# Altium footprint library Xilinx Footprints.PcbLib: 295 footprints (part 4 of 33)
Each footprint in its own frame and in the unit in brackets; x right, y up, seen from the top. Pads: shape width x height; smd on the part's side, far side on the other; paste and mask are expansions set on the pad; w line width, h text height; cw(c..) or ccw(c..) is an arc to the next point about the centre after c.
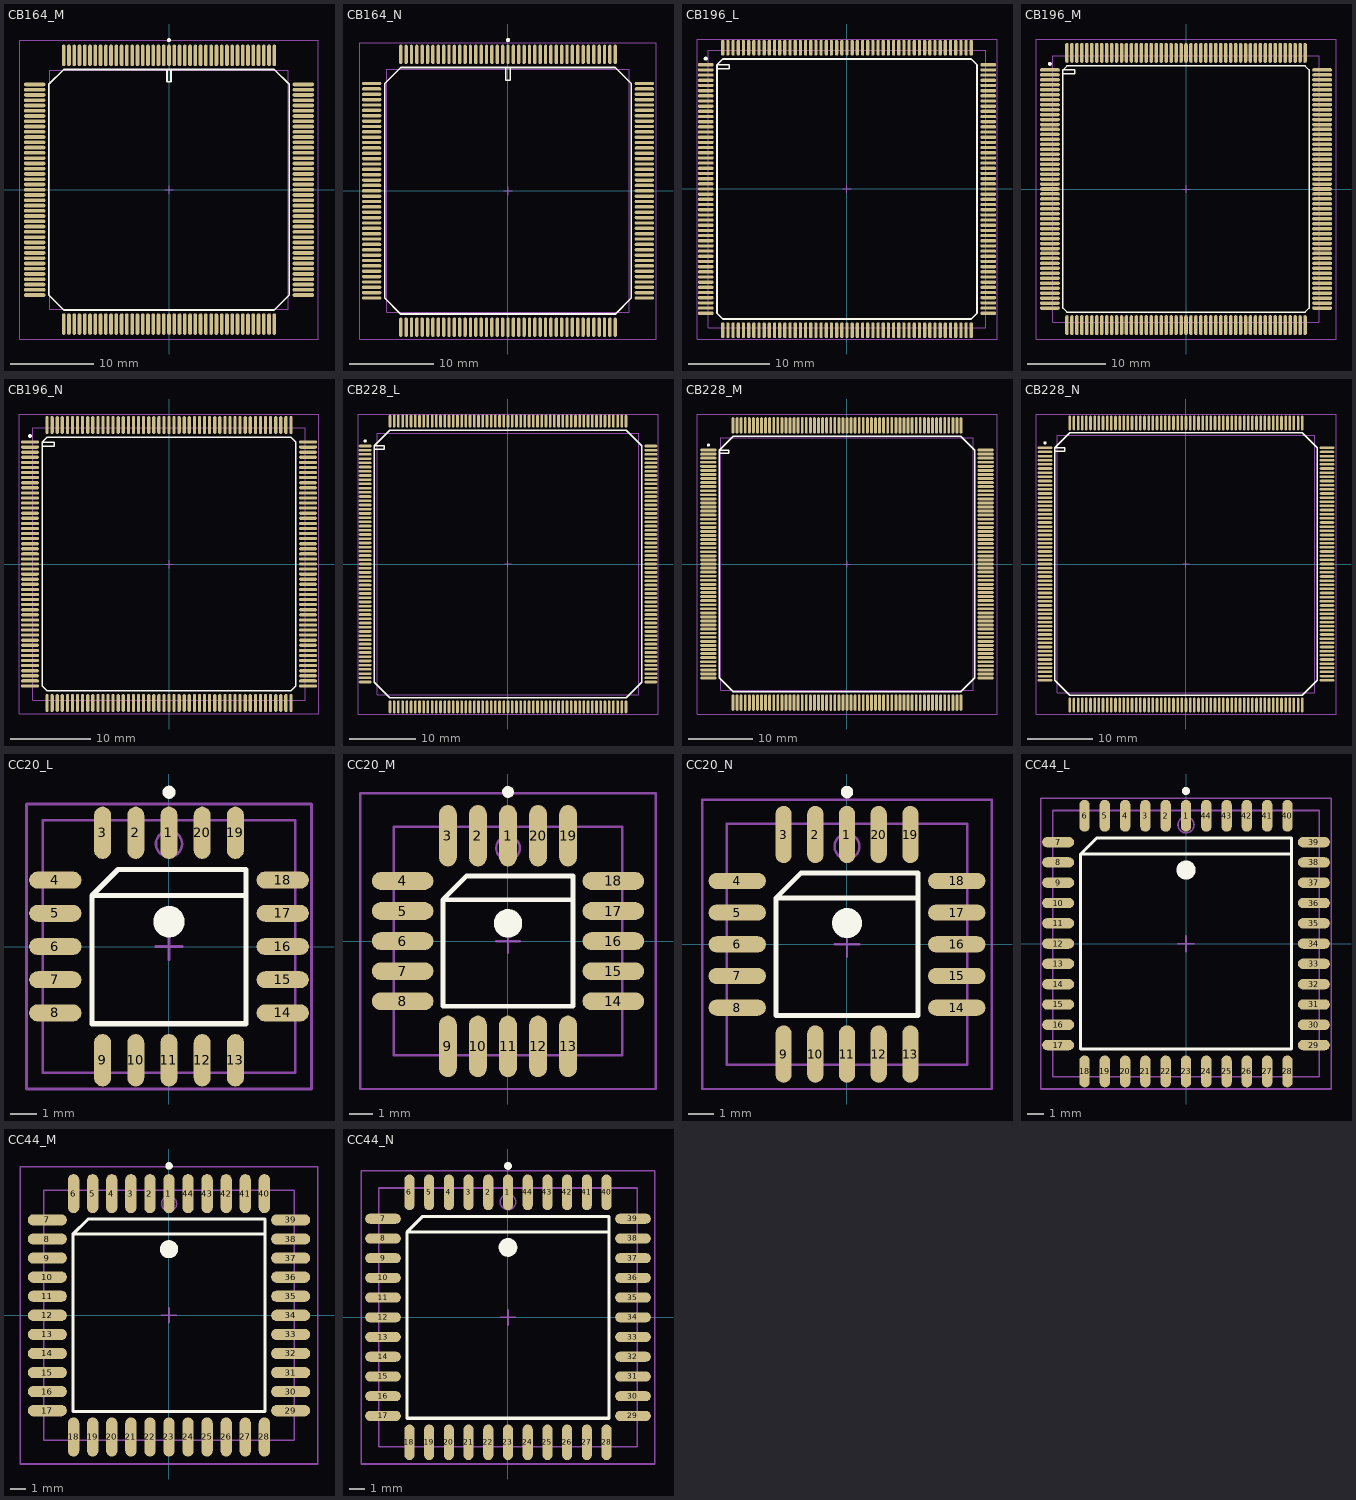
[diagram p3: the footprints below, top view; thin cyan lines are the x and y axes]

## CB164_M [mm] "164-Pin Ceramic Brazed Quad Flat Pack (CB164), IPC Low Density"
height 3.4
pads (164):
  oval 0.45x2.6 smd: 1(0,16.2) 2(-0.635,16.2) 3(-1.27,16.2) 4(-1.905,16.2) 5(-2.54,16.2) 6(-3.175,16.2) 7(-3.81,16.2) 8(-4.445,16.2) 9(-5.08,16.2) 10(-5.715,16.2) 11(-6.35,16.2) 12(-6.985,16.2) 13(-7.62,16.2) 14(-8.255,16.2) 15(-8.89,16.2) 16(-9.525,16.2) 17(-10.16,16.2) 18(-10.795,16.2) 19(-11.43,16.2) 20(-12.065,16.2) 21(-12.7,16.2) 63(-12.7,-16.2) 64(-12.065,-16.2) 65(-11.43,-16.2) 66(-10.795,-16.2) 67(-10.16,-16.2) 68(-9.525,-16.2) 69(-8.89,-16.2) 70(-8.255,-16.2) 71(-7.62,-16.2) 72(-6.985,-16.2) 73(-6.35,-16.2) 74(-5.715,-16.2) 75(-5.08,-16.2) 76(-4.445,-16.2) 77(-3.81,-16.2) 78(-3.175,-16.2) 79(-2.54,-16.2) 80(-1.905,-16.2) 81(-1.27,-16.2) 82(-0.635,-16.2) 83(0,-16.2) 84(0.635,-16.2) 85(1.27,-16.2) 86(1.905,-16.2) 87(2.54,-16.2) 88(3.175,-16.2) 89(3.81,-16.2) 90(4.445,-16.2) 91(5.08,-16.2) 92(5.715,-16.2) 93(6.35,-16.2) 94(6.985,-16.2) 95(7.62,-16.2) 96(8.255,-16.2) 97(8.89,-16.2) 98(9.525,-16.2) 99(10.16,-16.2) 100(10.795,-16.2) 101(11.43,-16.2) 102(12.065,-16.2) 103(12.7,-16.2) 145(12.7,16.2) 146(12.065,16.2) 147(11.43,16.2) 148(10.795,16.2) 149(10.16,16.2) 150(9.525,16.2) 151(8.89,16.2) 152(8.255,16.2) 153(7.62,16.2) 154(6.985,16.2) 155(6.35,16.2) 156(5.715,16.2) 157(5.08,16.2) 158(4.445,16.2) 159(3.81,16.2) 160(3.175,16.2) 161(2.54,16.2) 162(1.905,16.2) 163(1.27,16.2) 164(0.635,16.2)
  oval 2.6x0.45 smd: 22(-16.2,12.7) 23(-16.2,12.065) 24(-16.2,11.43) 25(-16.2,10.795) 26(-16.2,10.16) 27(-16.2,9.525) 28(-16.2,8.89) 29(-16.2,8.255) 30(-16.2,7.62) 31(-16.2,6.985) 32(-16.2,6.35) 33(-16.2,5.715) 34(-16.2,5.08) 35(-16.2,4.445) 36(-16.2,3.81) 37(-16.2,3.175) 38(-16.2,2.54) 39(-16.2,1.905) 40(-16.2,1.27) 41(-16.2,0.635) 42(-16.2,0) 43(-16.2,-0.635) 44(-16.2,-1.27) 45(-16.2,-1.905) 46(-16.2,-2.54) 47(-16.2,-3.175) 48(-16.2,-3.81) 49(-16.2,-4.445) 50(-16.2,-5.08) 51(-16.2,-5.715) 52(-16.2,-6.35) 53(-16.2,-6.985) 54(-16.2,-7.62) 55(-16.2,-8.255) 56(-16.2,-8.89) 57(-16.2,-9.525) 58(-16.2,-10.16) 59(-16.2,-10.795) 60(-16.2,-11.43) 61(-16.2,-12.065) 62(-16.2,-12.7) 104(16.2,-12.7) 105(16.2,-12.065) 106(16.2,-11.43) 107(16.2,-10.795) 108(16.2,-10.16) 109(16.2,-9.525) 110(16.2,-8.89) 111(16.2,-8.255) 112(16.2,-7.62) 113(16.2,-6.985) 114(16.2,-6.35) 115(16.2,-5.715) 116(16.2,-5.08) 117(16.2,-4.445) 118(16.2,-3.81) 119(16.2,-3.175) 120(16.2,-2.54) 121(16.2,-1.905) 122(16.2,-1.27) 123(16.2,-0.635) 124(16.2,0) 125(16.2,0.635) 126(16.2,1.27) 127(16.2,1.905) 128(16.2,2.54) 129(16.2,3.175) 130(16.2,3.81) 131(16.2,4.445) 132(16.2,5.08) 133(16.2,5.715) 134(16.2,6.35) 135(16.2,6.985) 136(16.2,7.62) 137(16.2,8.255) 138(16.2,8.89) 139(16.2,9.525) 140(16.2,10.16) 141(16.2,10.795) 142(16.2,11.43) 143(16.2,12.065) 144(16.2,12.7)
Top Overlay:
  circle w0.25: c0,18.05 r0.125
  lines w0.2: -0.25,14.5 -0.25,13 0.25,13 0.25,14.5 ; -14.5,-12.7 -12.7,-14.5 12.7,-14.5 14.5,-12.7 14.5,12.7 12.7,14.5 -12.7,14.5 -14.5,12.7 -14.5,-12.7
Mechanical 13:
  lines w0.1: -14.385,-14.385 14.385,-14.385 14.385,14.385 -14.385,14.385 -14.385,-14.385
Mechanical 15:
  lines w0.1: -0.5,0 0.5,0 ; 0,-0.5 0,0.5 ; -18,-18 18,-18 18,18 -18,18 -18,-18
3D body: height 3.4, standoff 0, extent -14.385,-14.385 14.385,14.385

## CB164_N [mm] "164-Pin Ceramic Brazed Quad Flat Pack (CB164), IPC Medium Density"
height 3.4
pads (164):
  oval 0.4x2.3 smd: 1(0,16.15) 2(-0.635,16.15) 3(-1.27,16.15) 4(-1.905,16.15) 5(-2.54,16.15) 6(-3.175,16.15) 7(-3.81,16.15) 8(-4.445,16.15) 9(-5.08,16.15) 10(-5.715,16.15) 11(-6.35,16.15) 12(-6.985,16.15) 13(-7.62,16.15) 14(-8.255,16.15) 15(-8.89,16.15) 16(-9.525,16.15) 17(-10.16,16.15) 18(-10.795,16.15) 19(-11.43,16.15) 20(-12.065,16.15) 21(-12.7,16.15) 63(-12.7,-16.15) 64(-12.065,-16.15) 65(-11.43,-16.15) 66(-10.795,-16.15) 67(-10.16,-16.15) 68(-9.525,-16.15) 69(-8.89,-16.15) 70(-8.255,-16.15) 71(-7.62,-16.15) 72(-6.985,-16.15) 73(-6.35,-16.15) 74(-5.715,-16.15) 75(-5.08,-16.15) 76(-4.445,-16.15) 77(-3.81,-16.15) 78(-3.175,-16.15) 79(-2.54,-16.15) 80(-1.905,-16.15) 81(-1.27,-16.15) 82(-0.635,-16.15) 83(0,-16.15) 84(0.635,-16.15) 85(1.27,-16.15) 86(1.905,-16.15) 87(2.54,-16.15) 88(3.175,-16.15) 89(3.81,-16.15) 90(4.445,-16.15) 91(5.08,-16.15) 92(5.715,-16.15) 93(6.35,-16.15) 94(6.985,-16.15) 95(7.62,-16.15) 96(8.255,-16.15) 97(8.89,-16.15) 98(9.525,-16.15) 99(10.16,-16.15) 100(10.795,-16.15) 101(11.43,-16.15) 102(12.065,-16.15) 103(12.7,-16.15) 145(12.7,16.15) 146(12.065,16.15) 147(11.43,16.15) 148(10.795,16.15) 149(10.16,16.15) 150(9.525,16.15) 151(8.89,16.15) 152(8.255,16.15) 153(7.62,16.15) 154(6.985,16.15) 155(6.35,16.15) 156(5.715,16.15) 157(5.08,16.15) 158(4.445,16.15) 159(3.81,16.15) 160(3.175,16.15) 161(2.54,16.15) 162(1.905,16.15) 163(1.27,16.15) 164(0.635,16.15)
  oval 2.3x0.4 smd: 22(-16.15,12.7) 23(-16.15,12.065) 24(-16.15,11.43) 25(-16.15,10.795) 26(-16.15,10.16) 27(-16.15,9.525) 28(-16.15,8.89) 29(-16.15,8.255) 30(-16.15,7.62) 31(-16.15,6.985) 32(-16.15,6.35) 33(-16.15,5.715) 34(-16.15,5.08) 35(-16.15,4.445) 36(-16.15,3.81) 37(-16.15,3.175) 38(-16.15,2.54) 39(-16.15,1.905) 40(-16.15,1.27) 41(-16.15,0.635) 42(-16.15,0) 43(-16.15,-0.635) 44(-16.15,-1.27) 45(-16.15,-1.905) 46(-16.15,-2.54) 47(-16.15,-3.175) 48(-16.15,-3.81) 49(-16.15,-4.445) 50(-16.15,-5.08) 51(-16.15,-5.715) 52(-16.15,-6.35) 53(-16.15,-6.985) 54(-16.15,-7.62) 55(-16.15,-8.255) 56(-16.15,-8.89) 57(-16.15,-9.525) 58(-16.15,-10.16) 59(-16.15,-10.795) 60(-16.15,-11.43) 61(-16.15,-12.065) 62(-16.15,-12.7) 104(16.15,-12.7) 105(16.15,-12.065) 106(16.15,-11.43) 107(16.15,-10.795) 108(16.15,-10.16) 109(16.15,-9.525) 110(16.15,-8.89) 111(16.15,-8.255) 112(16.15,-7.62) 113(16.15,-6.985) 114(16.15,-6.35) 115(16.15,-5.715) 116(16.15,-5.08) 117(16.15,-4.445) 118(16.15,-3.81) 119(16.15,-3.175) 120(16.15,-2.54) 121(16.15,-1.905) 122(16.15,-1.27) 123(16.15,-0.635) 124(16.15,0) 125(16.15,0.635) 126(16.15,1.27) 127(16.15,1.905) 128(16.15,2.54) 129(16.15,3.175) 130(16.15,3.81) 131(16.15,4.445) 132(16.15,5.08) 133(16.15,5.715) 134(16.15,6.35) 135(16.15,6.985) 136(16.15,7.62) 137(16.15,8.255) 138(16.15,8.89) 139(16.15,9.525) 140(16.15,10.16) 141(16.15,10.795) 142(16.15,11.43) 143(16.15,12.065) 144(16.15,12.7)
Top Overlay:
  circle w0.25: c0,17.85 r0.125
  lines w0.2: -0.25,14.6 -0.25,13.1 0.25,13.1 0.25,14.6 ; -14.6,-12.7 -12.7,-14.6 12.7,-14.6 14.6,-12.7 14.6,12.7 12.7,14.6 -12.7,14.6 -14.6,12.7 -14.6,-12.7
Mechanical 13:
  lines w0.1: -14.385,-14.385 14.385,-14.385 14.385,14.385 -14.385,14.385 -14.385,-14.385
Mechanical 15:
  lines w0.1: -0.5,0 0.5,0 ; 0,-0.5 0,0.5 ; -17.55,-17.55 17.55,-17.55 17.55,17.55 -17.55,17.55 -17.55,-17.55
3D body: height 3.4, standoff 0, extent -14.385,-14.385 14.385,14.385

## CB196_L [mm] "196-Pin Ceramic Brazed Quad Flat Pack (CB196), IPC High Density"
height 3.4
pads (196):
  oval 1.95x0.4 smd: 1(-17.325,15.24) 2(-17.325,14.605) 3(-17.325,13.97) 4(-17.325,13.335) 5(-17.325,12.7) 6(-17.325,12.065) 7(-17.325,11.43) 8(-17.325,10.795) 9(-17.325,10.16) 10(-17.325,9.525) 11(-17.325,8.89) 12(-17.325,8.255) 13(-17.325,7.62) 14(-17.325,6.985) 15(-17.325,6.35) 16(-17.325,5.715) 17(-17.325,5.08) 18(-17.325,4.445) 19(-17.325,3.81) 20(-17.325,3.175) 21(-17.325,2.54) 22(-17.325,1.905) 23(-17.325,1.27) 24(-17.325,0.635) 25(-17.325,0) 26(-17.325,-0.635) 27(-17.325,-1.27) 28(-17.325,-1.905) 29(-17.325,-2.54) 30(-17.325,-3.175) 31(-17.325,-3.81) 32(-17.325,-4.445) 33(-17.325,-5.08) 34(-17.325,-5.715) 35(-17.325,-6.35) 36(-17.325,-6.985) 37(-17.325,-7.62) 38(-17.325,-8.255) 39(-17.325,-8.89) 40(-17.325,-9.525) 41(-17.325,-10.16) 42(-17.325,-10.795) 43(-17.325,-11.43) 44(-17.325,-12.065) 45(-17.325,-12.7) 46(-17.325,-13.335) 47(-17.325,-13.97) 48(-17.325,-14.605) 49(-17.325,-15.24) 99(17.325,-15.24) 100(17.325,-14.605) 101(17.325,-13.97) 102(17.325,-13.335) 103(17.325,-12.7) 104(17.325,-12.065) 105(17.325,-11.43) 106(17.325,-10.795) 107(17.325,-10.16) 108(17.325,-9.525) 109(17.325,-8.89) 110(17.325,-8.255) 111(17.325,-7.62) 112(17.325,-6.985) 113(17.325,-6.35) 114(17.325,-5.715) 115(17.325,-5.08) 116(17.325,-4.445) 117(17.325,-3.81) 118(17.325,-3.175) 119(17.325,-2.54) 120(17.325,-1.905) 121(17.325,-1.27) 122(17.325,-0.635) 123(17.325,0) 124(17.325,0.635) 125(17.325,1.27) 126(17.325,1.905) 127(17.325,2.54) 128(17.325,3.175) 129(17.325,3.81) 130(17.325,4.445) 131(17.325,5.08) 132(17.325,5.715) 133(17.325,6.35) 134(17.325,6.985) 135(17.325,7.62) 136(17.325,8.255) 137(17.325,8.89) 138(17.325,9.525) 139(17.325,10.16) 140(17.325,10.795) 141(17.325,11.43) 142(17.325,12.065) 143(17.325,12.7) 144(17.325,13.335) 145(17.325,13.97) 146(17.325,14.605) 147(17.325,15.24)
  oval 0.4x1.95 smd: 50(-15.24,-17.325) 51(-14.605,-17.325) 52(-13.97,-17.325) 53(-13.335,-17.325) 54(-12.7,-17.325) 55(-12.065,-17.325) 56(-11.43,-17.325) 57(-10.795,-17.325) 58(-10.16,-17.325) 59(-9.525,-17.325) 60(-8.89,-17.325) 61(-8.255,-17.325) 62(-7.62,-17.325) 63(-6.985,-17.325) 64(-6.35,-17.325) 65(-5.715,-17.325) 66(-5.08,-17.325) 67(-4.445,-17.325) 68(-3.81,-17.325) 69(-3.175,-17.325) 70(-2.54,-17.325) 71(-1.905,-17.325) 72(-1.27,-17.325) 73(-0.635,-17.325) 74(0,-17.325) 75(0.635,-17.325) 76(1.27,-17.325) 77(1.905,-17.325) 78(2.54,-17.325) 79(3.175,-17.325) 80(3.81,-17.325) 81(4.445,-17.325) 82(5.08,-17.325) 83(5.715,-17.325) 84(6.35,-17.325) 85(6.985,-17.325) 86(7.62,-17.325) 87(8.255,-17.325) 88(8.89,-17.325) 89(9.525,-17.325) 90(10.16,-17.325) 91(10.795,-17.325) 92(11.43,-17.325) 93(12.065,-17.325) 94(12.7,-17.325) 95(13.335,-17.325) 96(13.97,-17.325) 97(14.605,-17.325) 98(15.24,-17.325) 148(15.24,17.325) 149(14.605,17.325) 150(13.97,17.325) 151(13.335,17.325) 152(12.7,17.325) 153(12.065,17.325) 154(11.43,17.325) 155(10.795,17.325) 156(10.16,17.325) 157(9.525,17.325) 158(8.89,17.325) 159(8.255,17.325) 160(7.62,17.325) 161(6.985,17.325) 162(6.35,17.325) 163(5.715,17.325) 164(5.08,17.325) 165(4.445,17.325) 166(3.81,17.325) 167(3.175,17.325) 168(2.54,17.325) 169(1.905,17.325) 170(1.27,17.325) 171(0.635,17.325) 172(0,17.325) 173(-0.635,17.325) 174(-1.27,17.325) 175(-1.905,17.325) 176(-2.54,17.325) 177(-3.175,17.325) 178(-3.81,17.325) 179(-4.445,17.325) 180(-5.08,17.325) 181(-5.715,17.325) 182(-6.35,17.325) 183(-6.985,17.325) 184(-7.62,17.325) 185(-8.255,17.325) 186(-8.89,17.325) 187(-9.525,17.325) 188(-10.16,17.325) 189(-10.795,17.325) 190(-11.43,17.325) 191(-12.065,17.325) 192(-12.7,17.325) 193(-13.335,17.325) 194(-13.97,17.325) 195(-14.605,17.325) 196(-15.24,17.325)
Top Overlay:
  circle w0.25: c-17.325,15.99 r0.125
  lines w0.2: -15.95,14.74 -14.45,14.74 -14.45,15.24 -15.95,15.24 ; -15.95,15.24 -15.95,-15.24 -15.24,-15.95 15.24,-15.95 15.95,-15.24 15.95,15.24 15.24,15.95 -15.24,15.95 -15.95,15.24
Mechanical 13:
  lines w0.1: -17.025,-17.025 -17.025,17.025 17.025,17.025 17.025,-17.025 -17.025,-17.025
Mechanical 15:
  lines w0.1: -0.5,0 0.5,0 ; 0,-0.5 0,0.5 ; -18.4,-18.4 -18.4,18.4 18.4,18.4 18.4,-18.4 -18.4,-18.4
3D body: height 3.4, standoff 0, extent -17.025,-17.025 17.025,17.025

## CB196_M [mm] "196-Pin Ceramic Brazed Quad Flat Pack (CB196), IPC Low Density"
height 3.4
pads (196):
  oval 2.55x0.45 smd: 1(-17.425,15.24) 2(-17.425,14.605) 3(-17.425,13.97) 4(-17.425,13.335) 5(-17.425,12.7) 6(-17.425,12.065) 7(-17.425,11.43) 8(-17.425,10.795) 9(-17.425,10.16) 10(-17.425,9.525) 11(-17.425,8.89) 12(-17.425,8.255) 13(-17.425,7.62) 14(-17.425,6.985) 15(-17.425,6.35) 16(-17.425,5.715) 17(-17.425,5.08) 18(-17.425,4.445) 19(-17.425,3.81) 20(-17.425,3.175) 21(-17.425,2.54) 22(-17.425,1.905) 23(-17.425,1.27) 24(-17.425,0.635) 25(-17.425,0) 26(-17.425,-0.635) 27(-17.425,-1.27) 28(-17.425,-1.905) 29(-17.425,-2.54) 30(-17.425,-3.175) 31(-17.425,-3.81) 32(-17.425,-4.445) 33(-17.425,-5.08) 34(-17.425,-5.715) 35(-17.425,-6.35) 36(-17.425,-6.985) 37(-17.425,-7.62) 38(-17.425,-8.255) 39(-17.425,-8.89) 40(-17.425,-9.525) 41(-17.425,-10.16) 42(-17.425,-10.795) 43(-17.425,-11.43) 44(-17.425,-12.065) 45(-17.425,-12.7) 46(-17.425,-13.335) 47(-17.425,-13.97) 48(-17.425,-14.605) 49(-17.425,-15.24) 99(17.425,-15.24) 100(17.425,-14.605) 101(17.425,-13.97) 102(17.425,-13.335) 103(17.425,-12.7) 104(17.425,-12.065) 105(17.425,-11.43) 106(17.425,-10.795) 107(17.425,-10.16) 108(17.425,-9.525) 109(17.425,-8.89) 110(17.425,-8.255) 111(17.425,-7.62) 112(17.425,-6.985) 113(17.425,-6.35) 114(17.425,-5.715) 115(17.425,-5.08) 116(17.425,-4.445) 117(17.425,-3.81) 118(17.425,-3.175) 119(17.425,-2.54) 120(17.425,-1.905) 121(17.425,-1.27) 122(17.425,-0.635) 123(17.425,0) 124(17.425,0.635) 125(17.425,1.27) 126(17.425,1.905) 127(17.425,2.54) 128(17.425,3.175) 129(17.425,3.81) 130(17.425,4.445) 131(17.425,5.08) 132(17.425,5.715) 133(17.425,6.35) 134(17.425,6.985) 135(17.425,7.62) 136(17.425,8.255) 137(17.425,8.89) 138(17.425,9.525) 139(17.425,10.16) 140(17.425,10.795) 141(17.425,11.43) 142(17.425,12.065) 143(17.425,12.7) 144(17.425,13.335) 145(17.425,13.97) 146(17.425,14.605) 147(17.425,15.24)
  oval 0.45x2.55 smd: 50(-15.24,-17.425) 51(-14.605,-17.425) 52(-13.97,-17.425) 53(-13.335,-17.425) 54(-12.7,-17.425) 55(-12.065,-17.425) 56(-11.43,-17.425) 57(-10.795,-17.425) 58(-10.16,-17.425) 59(-9.525,-17.425) 60(-8.89,-17.425) 61(-8.255,-17.425) 62(-7.62,-17.425) 63(-6.985,-17.425) 64(-6.35,-17.425) 65(-5.715,-17.425) 66(-5.08,-17.425) 67(-4.445,-17.425) 68(-3.81,-17.425) 69(-3.175,-17.425) 70(-2.54,-17.425) 71(-1.905,-17.425) 72(-1.27,-17.425) 73(-0.635,-17.425) 74(0,-17.425) 75(0.635,-17.425) 76(1.27,-17.425) 77(1.905,-17.425) 78(2.54,-17.425) 79(3.175,-17.425) 80(3.81,-17.425) 81(4.445,-17.425) 82(5.08,-17.425) 83(5.715,-17.425) 84(6.35,-17.425) 85(6.985,-17.425) 86(7.62,-17.425) 87(8.255,-17.425) 88(8.89,-17.425) 89(9.525,-17.425) 90(10.16,-17.425) 91(10.795,-17.425) 92(11.43,-17.425) 93(12.065,-17.425) 94(12.7,-17.425) 95(13.335,-17.425) 96(13.97,-17.425) 97(14.605,-17.425) 98(15.24,-17.425) 148(15.24,17.425) 149(14.605,17.425) 150(13.97,17.425) 151(13.335,17.425) 152(12.7,17.425) 153(12.065,17.425) 154(11.43,17.425) 155(10.795,17.425) 156(10.16,17.425) 157(9.525,17.425) 158(8.89,17.425) 159(8.255,17.425) 160(7.62,17.425) 161(6.985,17.425) 162(6.35,17.425) 163(5.715,17.425) 164(5.08,17.425) 165(4.445,17.425) 166(3.81,17.425) 167(3.175,17.425) 168(2.54,17.425) 169(1.905,17.425) 170(1.27,17.425) 171(0.635,17.425) 172(0,17.425) 173(-0.635,17.425) 174(-1.27,17.425) 175(-1.905,17.425) 176(-2.54,17.425) 177(-3.175,17.425) 178(-3.81,17.425) 179(-4.445,17.425) 180(-5.08,17.425) 181(-5.715,17.425) 182(-6.35,17.425) 183(-6.985,17.425) 184(-7.62,17.425) 185(-8.255,17.425) 186(-8.89,17.425) 187(-9.525,17.425) 188(-10.16,17.425) 189(-10.795,17.425) 190(-11.43,17.425) 191(-12.065,17.425) 192(-12.7,17.425) 193(-13.335,17.425) 194(-13.97,17.425) 195(-14.605,17.425) 196(-15.24,17.425)
Top Overlay:
  circle w0.25: c-17.425,16.015 r0.125
  lines w0.2: -15.75,14.74 -14.25,14.74 -14.25,15.24 -15.75,15.24 ; -15.75,15.24 -15.75,-15.24 -15.24,-15.75 15.24,-15.75 15.75,-15.24 15.75,15.24 15.24,15.75 -15.24,15.75 -15.75,15.24
Mechanical 13:
  lines w0.1: -17.025,-17.025 -17.025,17.025 17.025,17.025 17.025,-17.025 -17.025,-17.025
Mechanical 15:
  lines w0.1: -0.5,0 0.5,0 ; 0,-0.5 0,0.5 ; -19.2,-19.2 -19.2,19.2 19.2,19.2 19.2,-19.2 -19.2,-19.2
3D body: height 3.4, standoff 0, extent -17.025,-17.025 17.025,17.025

## CB196_N [mm] "196-Pin Ceramic Brazed Quad Flat Pack (CB196), IPC Medium Density"
height 3.4
pads (196):
  oval 2.25x0.4 smd: 1(-17.375,15.24) 2(-17.375,14.605) 3(-17.375,13.97) 4(-17.375,13.335) 5(-17.375,12.7) 6(-17.375,12.065) 7(-17.375,11.43) 8(-17.375,10.795) 9(-17.375,10.16) 10(-17.375,9.525) 11(-17.375,8.89) 12(-17.375,8.255) 13(-17.375,7.62) 14(-17.375,6.985) 15(-17.375,6.35) 16(-17.375,5.715) 17(-17.375,5.08) 18(-17.375,4.445) 19(-17.375,3.81) 20(-17.375,3.175) 21(-17.375,2.54) 22(-17.375,1.905) 23(-17.375,1.27) 24(-17.375,0.635) 25(-17.375,0) 26(-17.375,-0.635) 27(-17.375,-1.27) 28(-17.375,-1.905) 29(-17.375,-2.54) 30(-17.375,-3.175) 31(-17.375,-3.81) 32(-17.375,-4.445) 33(-17.375,-5.08) 34(-17.375,-5.715) 35(-17.375,-6.35) 36(-17.375,-6.985) 37(-17.375,-7.62) 38(-17.375,-8.255) 39(-17.375,-8.89) 40(-17.375,-9.525) 41(-17.375,-10.16) 42(-17.375,-10.795) 43(-17.375,-11.43) 44(-17.375,-12.065) 45(-17.375,-12.7) 46(-17.375,-13.335) 47(-17.375,-13.97) 48(-17.375,-14.605) 49(-17.375,-15.24) 99(17.375,-15.24) 100(17.375,-14.605) 101(17.375,-13.97) 102(17.375,-13.335) 103(17.375,-12.7) 104(17.375,-12.065) 105(17.375,-11.43) 106(17.375,-10.795) 107(17.375,-10.16) 108(17.375,-9.525) 109(17.375,-8.89) 110(17.375,-8.255) 111(17.375,-7.62) 112(17.375,-6.985) 113(17.375,-6.35) 114(17.375,-5.715) 115(17.375,-5.08) 116(17.375,-4.445) 117(17.375,-3.81) 118(17.375,-3.175) 119(17.375,-2.54) 120(17.375,-1.905) 121(17.375,-1.27) 122(17.375,-0.635) 123(17.375,0) 124(17.375,0.635) 125(17.375,1.27) 126(17.375,1.905) 127(17.375,2.54) 128(17.375,3.175) 129(17.375,3.81) 130(17.375,4.445) 131(17.375,5.08) 132(17.375,5.715) 133(17.375,6.35) 134(17.375,6.985) 135(17.375,7.62) 136(17.375,8.255) 137(17.375,8.89) 138(17.375,9.525) 139(17.375,10.16) 140(17.375,10.795) 141(17.375,11.43) 142(17.375,12.065) 143(17.375,12.7) 144(17.375,13.335) 145(17.375,13.97) 146(17.375,14.605) 147(17.375,15.24)
  oval 0.4x2.25 smd: 50(-15.24,-17.375) 51(-14.605,-17.375) 52(-13.97,-17.375) 53(-13.335,-17.375) 54(-12.7,-17.375) 55(-12.065,-17.375) 56(-11.43,-17.375) 57(-10.795,-17.375) 58(-10.16,-17.375) 59(-9.525,-17.375) 60(-8.89,-17.375) 61(-8.255,-17.375) 62(-7.62,-17.375) 63(-6.985,-17.375) 64(-6.35,-17.375) 65(-5.715,-17.375) 66(-5.08,-17.375) 67(-4.445,-17.375) 68(-3.81,-17.375) 69(-3.175,-17.375) 70(-2.54,-17.375) 71(-1.905,-17.375) 72(-1.27,-17.375) 73(-0.635,-17.375) 74(0,-17.375) 75(0.635,-17.375) 76(1.27,-17.375) 77(1.905,-17.375) 78(2.54,-17.375) 79(3.175,-17.375) 80(3.81,-17.375) 81(4.445,-17.375) 82(5.08,-17.375) 83(5.715,-17.375) 84(6.35,-17.375) 85(6.985,-17.375) 86(7.62,-17.375) 87(8.255,-17.375) 88(8.89,-17.375) 89(9.525,-17.375) 90(10.16,-17.375) 91(10.795,-17.375) 92(11.43,-17.375) 93(12.065,-17.375) 94(12.7,-17.375) 95(13.335,-17.375) 96(13.97,-17.375) 97(14.605,-17.375) 98(15.24,-17.375) 148(15.24,17.375) 149(14.605,17.375) 150(13.97,17.375) 151(13.335,17.375) 152(12.7,17.375) 153(12.065,17.375) 154(11.43,17.375) 155(10.795,17.375) 156(10.16,17.375) 157(9.525,17.375) 158(8.89,17.375) 159(8.255,17.375) 160(7.62,17.375) 161(6.985,17.375) 162(6.35,17.375) 163(5.715,17.375) 164(5.08,17.375) 165(4.445,17.375) 166(3.81,17.375) 167(3.175,17.375) 168(2.54,17.375) 169(1.905,17.375) 170(1.27,17.375) 171(0.635,17.375) 172(0,17.375) 173(-0.635,17.375) 174(-1.27,17.375) 175(-1.905,17.375) 176(-2.54,17.375) 177(-3.175,17.375) 178(-3.81,17.375) 179(-4.445,17.375) 180(-5.08,17.375) 181(-5.715,17.375) 182(-6.35,17.375) 183(-6.985,17.375) 184(-7.62,17.375) 185(-8.255,17.375) 186(-8.89,17.375) 187(-9.525,17.375) 188(-10.16,17.375) 189(-10.795,17.375) 190(-11.43,17.375) 191(-12.065,17.375) 192(-12.7,17.375) 193(-13.335,17.375) 194(-13.97,17.375) 195(-14.605,17.375) 196(-15.24,17.375)
Top Overlay:
  circle w0.25: c-17.375,15.99 r0.125
  lines w0.2: -15.85,14.74 -14.35,14.74 -14.35,15.24 -15.85,15.24 ; -15.85,15.24 -15.85,-15.24 -15.24,-15.85 15.24,-15.85 15.85,-15.24 15.85,15.24 15.24,15.85 -15.24,15.85 -15.85,15.24
Mechanical 13:
  lines w0.1: -17.025,-17.025 -17.025,17.025 17.025,17.025 17.025,-17.025 -17.025,-17.025
Mechanical 15:
  lines w0.1: -0.5,0 0.5,0 ; 0,-0.5 0,0.5 ; -18.75,-18.75 -18.75,18.75 18.75,18.75 18.75,-18.75 -18.75,-18.75
3D body: height 3.4, standoff 0, extent -17.025,-17.025 17.025,17.025

## CB228_L [mm] "228-Pin Ceramic Brazed Quad Flat Pack (CB228), IPC High Density"
height 3.4
pads (228):
  oval 1.95x0.4 smd: 1(-21.525,17.78) 2(-21.525,17.145) 3(-21.525,16.51) 4(-21.525,15.875) 5(-21.525,15.24) 6(-21.525,14.605) 7(-21.525,13.97) 8(-21.525,13.335) 9(-21.525,12.7) 10(-21.525,12.065) 11(-21.525,11.43) 12(-21.525,10.795) 13(-21.525,10.16) 14(-21.525,9.525) 15(-21.525,8.89) 16(-21.525,8.255) 17(-21.525,7.62) 18(-21.525,6.985) 19(-21.525,6.35) 20(-21.525,5.715) 21(-21.525,5.08) 22(-21.525,4.445) 23(-21.525,3.81) 24(-21.525,3.175) 25(-21.525,2.54) 26(-21.525,1.905) 27(-21.525,1.27) 28(-21.525,0.635) 29(-21.525,0) 30(-21.525,-0.635) 31(-21.525,-1.27) 32(-21.525,-1.905) 33(-21.525,-2.54) 34(-21.525,-3.175) 35(-21.525,-3.81) 36(-21.525,-4.445) 37(-21.525,-5.08) 38(-21.525,-5.715) 39(-21.525,-6.35) 40(-21.525,-6.985) 41(-21.525,-7.62) 42(-21.525,-8.255) 43(-21.525,-8.89) 44(-21.525,-9.525) 45(-21.525,-10.16) 46(-21.525,-10.795) 47(-21.525,-11.43) 48(-21.525,-12.065) 49(-21.525,-12.7) 50(-21.525,-13.335) 51(-21.525,-13.97) 52(-21.525,-14.605) 53(-21.525,-15.24) 54(-21.525,-15.875) 55(-21.525,-16.51) 56(-21.525,-17.145) 57(-21.525,-17.78) 115(21.525,-17.78) 116(21.525,-17.145) 117(21.525,-16.51) 118(21.525,-15.875) 119(21.525,-15.24) 120(21.525,-14.605) 121(21.525,-13.97) 122(21.525,-13.335) 123(21.525,-12.7) 124(21.525,-12.065) 125(21.525,-11.43) 126(21.525,-10.795) 127(21.525,-10.16) 128(21.525,-9.525) 129(21.525,-8.89) 130(21.525,-8.255) 131(21.525,-7.62) 132(21.525,-6.985) 133(21.525,-6.35) 134(21.525,-5.715) 135(21.525,-5.08) 136(21.525,-4.445) 137(21.525,-3.81) 138(21.525,-3.175) 139(21.525,-2.54) 140(21.525,-1.905) 141(21.525,-1.27) 142(21.525,-0.635) 143(21.525,0) 144(21.525,0.635) 145(21.525,1.27) 146(21.525,1.905) 147(21.525,2.54) 148(21.525,3.175) 149(21.525,3.81) 150(21.525,4.445) 151(21.525,5.08) 152(21.525,5.715) 153(21.525,6.35) 154(21.525,6.985) 155(21.525,7.62) 156(21.525,8.255) 157(21.525,8.89) 158(21.525,9.525) 159(21.525,10.16) 160(21.525,10.795) 161(21.525,11.43) 162(21.525,12.065) 163(21.525,12.7) 164(21.525,13.335) 165(21.525,13.97) 166(21.525,14.605) 167(21.525,15.24) 168(21.525,15.875) 169(21.525,16.51) 170(21.525,17.145) 171(21.525,17.78)
  oval 0.4x1.95 smd: 58(-17.78,-21.525) 59(-17.145,-21.525) 60(-16.51,-21.525) 61(-15.875,-21.525) 62(-15.24,-21.525) 63(-14.605,-21.525) 64(-13.97,-21.525) 65(-13.335,-21.525) 66(-12.7,-21.525) 67(-12.065,-21.525) 68(-11.43,-21.525) 69(-10.795,-21.525) 70(-10.16,-21.525) 71(-9.525,-21.525) 72(-8.89,-21.525) 73(-8.255,-21.525) 74(-7.62,-21.525) 75(-6.985,-21.525) 76(-6.35,-21.525) 77(-5.715,-21.525) 78(-5.08,-21.525) 79(-4.445,-21.525) 80(-3.81,-21.525) 81(-3.175,-21.525) 82(-2.54,-21.525) 83(-1.905,-21.525) 84(-1.27,-21.525) 85(-0.635,-21.525) 86(0,-21.525) 87(0.635,-21.525) 88(1.27,-21.525) 89(1.905,-21.525) 90(2.54,-21.525) 91(3.175,-21.525) 92(3.81,-21.525) 93(4.445,-21.525) 94(5.08,-21.525) 95(5.715,-21.525) 96(6.35,-21.525) 97(6.985,-21.525) 98(7.62,-21.525) 99(8.255,-21.525) 100(8.89,-21.525) 101(9.525,-21.525) 102(10.16,-21.525) 103(10.795,-21.525) 104(11.43,-21.525) 105(12.065,-21.525) 106(12.7,-21.525) 107(13.335,-21.525) 108(13.97,-21.525) 109(14.605,-21.525) 110(15.24,-21.525) 111(15.875,-21.525) 112(16.51,-21.525) 113(17.145,-21.525) 114(17.78,-21.525) 172(17.78,21.525) 173(17.145,21.525) 174(16.51,21.525) 175(15.875,21.525) 176(15.24,21.525) 177(14.605,21.525) 178(13.97,21.525) 179(13.335,21.525) 180(12.7,21.525) 181(12.065,21.525) 182(11.43,21.525) 183(10.795,21.525) 184(10.16,21.525) 185(9.525,21.525) 186(8.89,21.525) 187(8.255,21.525) 188(7.62,21.525) 189(6.985,21.525) 190(6.35,21.525) 191(5.715,21.525) 192(5.08,21.525) 193(4.445,21.525) 194(3.81,21.525) 195(3.175,21.525) 196(2.54,21.525) 197(1.905,21.525) 198(1.27,21.525) 199(0.635,21.525) 200(0,21.525) 201(-0.635,21.525) 202(-1.27,21.525) 203(-1.905,21.525) 204(-2.54,21.525) 205(-3.175,21.525) 206(-3.81,21.525) 207(-4.445,21.525) 208(-5.08,21.525) 209(-5.715,21.525) 210(-6.35,21.525) 211(-6.985,21.525) 212(-7.62,21.525) 213(-8.255,21.525) 214(-8.89,21.525) 215(-9.525,21.525) 216(-10.16,21.525) 217(-10.795,21.525) 218(-11.43,21.525) 219(-12.065,21.525) 220(-12.7,21.525) 221(-13.335,21.525) 222(-13.97,21.525) 223(-14.605,21.525) 224(-15.24,21.525) 225(-15.875,21.525) 226(-16.51,21.525) 227(-17.145,21.525) 228(-17.78,21.525)
Top Overlay:
  circle w0.25: c-21.525,18.53 r0.125
  lines w0.2: -20.15,17.28 -18.65,17.28 -18.65,17.78 -20.15,17.78 ; -20.15,17.78 -17.78,20.15 17.78,20.15 20.15,17.78 20.15,-17.78 17.78,-20.15 -17.78,-20.15 -20.15,-17.78 -20.15,17.78
Mechanical 13:
  lines w0.1: -19.71,-19.71 19.71,-19.71 19.71,19.71 -19.71,19.71 -19.71,-19.71
Mechanical 15:
  lines w0.1: -0.5,0 0.5,0 ; 0,-0.5 0,0.5 ; -22.6,-22.6 22.6,-22.6 22.6,22.6 -22.6,22.6 -22.6,-22.6
3D body: height 3.4, standoff 0, extent -19.71,-19.71 19.71,19.71

## CB228_M [mm] "228-Pin Ceramic Brazed Quad Flat Pack (CB228), IPC Low Density"
height 3.4
pads (228):
  oval 2.55x0.45 smd: 1(-21.625,17.78) 2(-21.625,17.145) 3(-21.625,16.51) 4(-21.625,15.875) 5(-21.625,15.24) 6(-21.625,14.605) 7(-21.625,13.97) 8(-21.625,13.335) 9(-21.625,12.7) 10(-21.625,12.065) 11(-21.625,11.43) 12(-21.625,10.795) 13(-21.625,10.16) 14(-21.625,9.525) 15(-21.625,8.89) 16(-21.625,8.255) 17(-21.625,7.62) 18(-21.625,6.985) 19(-21.625,6.35) 20(-21.625,5.715) 21(-21.625,5.08) 22(-21.625,4.445) 23(-21.625,3.81) 24(-21.625,3.175) 25(-21.625,2.54) 26(-21.625,1.905) 27(-21.625,1.27) 28(-21.625,0.635) 29(-21.625,0) 30(-21.625,-0.635) 31(-21.625,-1.27) 32(-21.625,-1.905) 33(-21.625,-2.54) 34(-21.625,-3.175) 35(-21.625,-3.81) 36(-21.625,-4.445) 37(-21.625,-5.08) 38(-21.625,-5.715) 39(-21.625,-6.35) 40(-21.625,-6.985) 41(-21.625,-7.62) 42(-21.625,-8.255) 43(-21.625,-8.89) 44(-21.625,-9.525) 45(-21.625,-10.16) 46(-21.625,-10.795) 47(-21.625,-11.43) 48(-21.625,-12.065) 49(-21.625,-12.7) 50(-21.625,-13.335) 51(-21.625,-13.97) 52(-21.625,-14.605) 53(-21.625,-15.24) 54(-21.625,-15.875) 55(-21.625,-16.51) 56(-21.625,-17.145) 57(-21.625,-17.78) 115(21.625,-17.78) 116(21.625,-17.145) 117(21.625,-16.51) 118(21.625,-15.875) 119(21.625,-15.24) 120(21.625,-14.605) 121(21.625,-13.97) 122(21.625,-13.335) 123(21.625,-12.7) 124(21.625,-12.065) 125(21.625,-11.43) 126(21.625,-10.795) 127(21.625,-10.16) 128(21.625,-9.525) 129(21.625,-8.89) 130(21.625,-8.255) 131(21.625,-7.62) 132(21.625,-6.985) 133(21.625,-6.35) 134(21.625,-5.715) 135(21.625,-5.08) 136(21.625,-4.445) 137(21.625,-3.81) 138(21.625,-3.175) 139(21.625,-2.54) 140(21.625,-1.905) 141(21.625,-1.27) 142(21.625,-0.635) 143(21.625,0) 144(21.625,0.635) 145(21.625,1.27) 146(21.625,1.905) 147(21.625,2.54) 148(21.625,3.175) 149(21.625,3.81) 150(21.625,4.445) 151(21.625,5.08) 152(21.625,5.715) 153(21.625,6.35) 154(21.625,6.985) 155(21.625,7.62) 156(21.625,8.255) 157(21.625,8.89) 158(21.625,9.525) 159(21.625,10.16) 160(21.625,10.795) 161(21.625,11.43) 162(21.625,12.065) 163(21.625,12.7) 164(21.625,13.335) 165(21.625,13.97) 166(21.625,14.605) 167(21.625,15.24) 168(21.625,15.875) 169(21.625,16.51) 170(21.625,17.145) 171(21.625,17.78)
  oval 0.45x2.55 smd: 58(-17.78,-21.625) 59(-17.145,-21.625) 60(-16.51,-21.625) 61(-15.875,-21.625) 62(-15.24,-21.625) 63(-14.605,-21.625) 64(-13.97,-21.625) 65(-13.335,-21.625) 66(-12.7,-21.625) 67(-12.065,-21.625) 68(-11.43,-21.625) 69(-10.795,-21.625) 70(-10.16,-21.625) 71(-9.525,-21.625) 72(-8.89,-21.625) 73(-8.255,-21.625) 74(-7.62,-21.625) 75(-6.985,-21.625) 76(-6.35,-21.625) 77(-5.715,-21.625) 78(-5.08,-21.625) 79(-4.445,-21.625) 80(-3.81,-21.625) 81(-3.175,-21.625) 82(-2.54,-21.625) 83(-1.905,-21.625) 84(-1.27,-21.625) 85(-0.635,-21.625) 86(0,-21.625) 87(0.635,-21.625) 88(1.27,-21.625) 89(1.905,-21.625) 90(2.54,-21.625) 91(3.175,-21.625) 92(3.81,-21.625) 93(4.445,-21.625) 94(5.08,-21.625) 95(5.715,-21.625) 96(6.35,-21.625) 97(6.985,-21.625) 98(7.62,-21.625) 99(8.255,-21.625) 100(8.89,-21.625) 101(9.525,-21.625) 102(10.16,-21.625) 103(10.795,-21.625) 104(11.43,-21.625) 105(12.065,-21.625) 106(12.7,-21.625) 107(13.335,-21.625) 108(13.97,-21.625) 109(14.605,-21.625) 110(15.24,-21.625) 111(15.875,-21.625) 112(16.51,-21.625) 113(17.145,-21.625) 114(17.78,-21.625) 172(17.78,21.625) 173(17.145,21.625) 174(16.51,21.625) 175(15.875,21.625) 176(15.24,21.625) 177(14.605,21.625) 178(13.97,21.625) 179(13.335,21.625) 180(12.7,21.625) 181(12.065,21.625) 182(11.43,21.625) 183(10.795,21.625) 184(10.16,21.625) 185(9.525,21.625) 186(8.89,21.625) 187(8.255,21.625) 188(7.62,21.625) 189(6.985,21.625) 190(6.35,21.625) 191(5.715,21.625) 192(5.08,21.625) 193(4.445,21.625) 194(3.81,21.625) 195(3.175,21.625) 196(2.54,21.625) 197(1.905,21.625) 198(1.27,21.625) 199(0.635,21.625) 200(0,21.625) 201(-0.635,21.625) 202(-1.27,21.625) 203(-1.905,21.625) 204(-2.54,21.625) 205(-3.175,21.625) 206(-3.81,21.625) 207(-4.445,21.625) 208(-5.08,21.625) 209(-5.715,21.625) 210(-6.35,21.625) 211(-6.985,21.625) 212(-7.62,21.625) 213(-8.255,21.625) 214(-8.89,21.625) 215(-9.525,21.625) 216(-10.16,21.625) 217(-10.795,21.625) 218(-11.43,21.625) 219(-12.065,21.625) 220(-12.7,21.625) 221(-13.335,21.625) 222(-13.97,21.625) 223(-14.605,21.625) 224(-15.24,21.625) 225(-15.875,21.625) 226(-16.51,21.625) 227(-17.145,21.625) 228(-17.78,21.625)
Top Overlay:
  circle w0.25: c-21.625,18.555 r0.125
  lines w0.2: -19.95,17.28 -18.45,17.28 -18.45,17.78 -19.95,17.78 ; -19.95,17.78 -17.78,19.95 17.78,19.95 19.95,17.78 19.95,-17.78 17.78,-19.95 -17.78,-19.95 -19.95,-17.78 -19.95,17.78
Mechanical 13:
  lines w0.1: -19.71,-19.71 19.71,-19.71 19.71,19.71 -19.71,19.71 -19.71,-19.71
Mechanical 15:
  lines w0.1: -0.5,0 0.5,0 ; 0,-0.5 0,0.5 ; -23.4,-23.4 23.4,-23.4 23.4,23.4 -23.4,23.4 -23.4,-23.4
3D body: height 3.4, standoff 0, extent -19.71,-19.71 19.71,19.71

## CB228_N [mm] "228-Pin Ceramic Brazed Quad Flat Pack (CB228), IPC Medium Density"
height 3.4
pads (228):
  oval 2.25x0.4 smd: 1(-21.575,17.78) 2(-21.575,17.145) 3(-21.575,16.51) 4(-21.575,15.875) 5(-21.575,15.24) 6(-21.575,14.605) 7(-21.575,13.97) 8(-21.575,13.335) 9(-21.575,12.7) 10(-21.575,12.065) 11(-21.575,11.43) 12(-21.575,10.795) 13(-21.575,10.16) 14(-21.575,9.525) 15(-21.575,8.89) 16(-21.575,8.255) 17(-21.575,7.62) 18(-21.575,6.985) 19(-21.575,6.35) 20(-21.575,5.715) 21(-21.575,5.08) 22(-21.575,4.445) 23(-21.575,3.81) 24(-21.575,3.175) 25(-21.575,2.54) 26(-21.575,1.905) 27(-21.575,1.27) 28(-21.575,0.635) 29(-21.575,0) 30(-21.575,-0.635) 31(-21.575,-1.27) 32(-21.575,-1.905) 33(-21.575,-2.54) 34(-21.575,-3.175) 35(-21.575,-3.81) 36(-21.575,-4.445) 37(-21.575,-5.08) 38(-21.575,-5.715) 39(-21.575,-6.35) 40(-21.575,-6.985) 41(-21.575,-7.62) 42(-21.575,-8.255) 43(-21.575,-8.89) 44(-21.575,-9.525) 45(-21.575,-10.16) 46(-21.575,-10.795) 47(-21.575,-11.43) 48(-21.575,-12.065) 49(-21.575,-12.7) 50(-21.575,-13.335) 51(-21.575,-13.97) 52(-21.575,-14.605) 53(-21.575,-15.24) 54(-21.575,-15.875) 55(-21.575,-16.51) 56(-21.575,-17.145) 57(-21.575,-17.78) 115(21.575,-17.78) 116(21.575,-17.145) 117(21.575,-16.51) 118(21.575,-15.875) 119(21.575,-15.24) 120(21.575,-14.605) 121(21.575,-13.97) 122(21.575,-13.335) 123(21.575,-12.7) 124(21.575,-12.065) 125(21.575,-11.43) 126(21.575,-10.795) 127(21.575,-10.16) 128(21.575,-9.525) 129(21.575,-8.89) 130(21.575,-8.255) 131(21.575,-7.62) 132(21.575,-6.985) 133(21.575,-6.35) 134(21.575,-5.715) 135(21.575,-5.08) 136(21.575,-4.445) 137(21.575,-3.81) 138(21.575,-3.175) 139(21.575,-2.54) 140(21.575,-1.905) 141(21.575,-1.27) 142(21.575,-0.635) 143(21.575,0) 144(21.575,0.635) 145(21.575,1.27) 146(21.575,1.905) 147(21.575,2.54) 148(21.575,3.175) 149(21.575,3.81) 150(21.575,4.445) 151(21.575,5.08) 152(21.575,5.715) 153(21.575,6.35) 154(21.575,6.985) 155(21.575,7.62) 156(21.575,8.255) 157(21.575,8.89) 158(21.575,9.525) 159(21.575,10.16) 160(21.575,10.795) 161(21.575,11.43) 162(21.575,12.065) 163(21.575,12.7) 164(21.575,13.335) 165(21.575,13.97) 166(21.575,14.605) 167(21.575,15.24) 168(21.575,15.875) 169(21.575,16.51) 170(21.575,17.145) 171(21.575,17.78)
  oval 0.4x2.25 smd: 58(-17.78,-21.575) 59(-17.145,-21.575) 60(-16.51,-21.575) 61(-15.875,-21.575) 62(-15.24,-21.575) 63(-14.605,-21.575) 64(-13.97,-21.575) 65(-13.335,-21.575) 66(-12.7,-21.575) 67(-12.065,-21.575) 68(-11.43,-21.575) 69(-10.795,-21.575) 70(-10.16,-21.575) 71(-9.525,-21.575) 72(-8.89,-21.575) 73(-8.255,-21.575) 74(-7.62,-21.575) 75(-6.985,-21.575) 76(-6.35,-21.575) 77(-5.715,-21.575) 78(-5.08,-21.575) 79(-4.445,-21.575) 80(-3.81,-21.575) 81(-3.175,-21.575) 82(-2.54,-21.575) 83(-1.905,-21.575) 84(-1.27,-21.575) 85(-0.635,-21.575) 86(0,-21.575) 87(0.635,-21.575) 88(1.27,-21.575) 89(1.905,-21.575) 90(2.54,-21.575) 91(3.175,-21.575) 92(3.81,-21.575) 93(4.445,-21.575) 94(5.08,-21.575) 95(5.715,-21.575) 96(6.35,-21.575) 97(6.985,-21.575) 98(7.62,-21.575) 99(8.255,-21.575) 100(8.89,-21.575) 101(9.525,-21.575) 102(10.16,-21.575) 103(10.795,-21.575) 104(11.43,-21.575) 105(12.065,-21.575) 106(12.7,-21.575) 107(13.335,-21.575) 108(13.97,-21.575) 109(14.605,-21.575) 110(15.24,-21.575) 111(15.875,-21.575) 112(16.51,-21.575) 113(17.145,-21.575) 114(17.78,-21.575) 172(17.78,21.575) 173(17.145,21.575) 174(16.51,21.575) 175(15.875,21.575) 176(15.24,21.575) 177(14.605,21.575) 178(13.97,21.575) 179(13.335,21.575) 180(12.7,21.575) 181(12.065,21.575) 182(11.43,21.575) 183(10.795,21.575) 184(10.16,21.575) 185(9.525,21.575) 186(8.89,21.575) 187(8.255,21.575) 188(7.62,21.575) 189(6.985,21.575) 190(6.35,21.575) 191(5.715,21.575) 192(5.08,21.575) 193(4.445,21.575) 194(3.81,21.575) 195(3.175,21.575) 196(2.54,21.575) 197(1.905,21.575) 198(1.27,21.575) 199(0.635,21.575) 200(0,21.575) 201(-0.635,21.575) 202(-1.27,21.575) 203(-1.905,21.575) 204(-2.54,21.575) 205(-3.175,21.575) 206(-3.81,21.575) 207(-4.445,21.575) 208(-5.08,21.575) 209(-5.715,21.575) 210(-6.35,21.575) 211(-6.985,21.575) 212(-7.62,21.575) 213(-8.255,21.575) 214(-8.89,21.575) 215(-9.525,21.575) 216(-10.16,21.575) 217(-10.795,21.575) 218(-11.43,21.575) 219(-12.065,21.575) 220(-12.7,21.575) 221(-13.335,21.575) 222(-13.97,21.575) 223(-14.605,21.575) 224(-15.24,21.575) 225(-15.875,21.575) 226(-16.51,21.575) 227(-17.145,21.575) 228(-17.78,21.575)
Top Overlay:
  circle w0.25: c-21.575,18.53 r0.125
  lines w0.2: -20.05,17.28 -18.55,17.28 -18.55,17.78 -20.05,17.78 ; -20.05,17.78 -17.78,20.05 17.78,20.05 20.05,17.78 20.05,-17.78 17.78,-20.05 -17.78,-20.05 -20.05,-17.78 -20.05,17.78
Mechanical 13:
  lines w0.1: -19.71,-19.71 19.71,-19.71 19.71,19.71 -19.71,19.71 -19.71,-19.71
Mechanical 15:
  lines w0.1: -0.5,0 0.5,0 ; 0,-0.5 0,0.5 ; -22.95,-22.95 22.95,-22.95 22.95,22.95 -22.95,22.95 -22.95,-22.95
3D body: height 3.4, standoff 0, extent -19.71,-19.71 19.71,19.71

## CC20_L [mm] "20-Pin Ceramic Leaded Chip Carrier (CC20), IPC High Density"
height 3.94
pads (20):
  oval 0.65x2 smd: 1(0,4.35) 2(-1.27,4.35) 3(-2.54,4.35) 9(-2.54,-4.35) 10(-1.27,-4.35) 11(0,-4.35) 12(1.27,-4.35) 13(2.54,-4.35) 19(2.54,4.35) 20(1.27,4.35)
  oval 2x0.65 smd: 4(-4.35,2.54) 5(-4.35,1.27) 6(-4.35,0) 7(-4.35,-1.27) 8(-4.35,-2.54) 14(4.35,-2.54) 15(4.35,-1.27) 16(4.35,0) 17(4.35,1.27) 18(4.35,2.54)
Top Overlay:
  circle w0.6: c0,0.95 r0.3
  circle w0.25: c0,5.9 r0.125
  lines w0.2: 2.95,1.95 -2.95,1.95 ; -2.95,1.95 -2.95,-2.95 2.95,-2.95 2.95,2.95 -1.95,2.95 -2.95,1.95
Mechanical 13:
  circle w0.1: c0,3.925 r0.5
  lines w0.1: -4.825,-4.825 4.825,-4.825 4.825,4.825 -4.825,4.825 -4.825,-4.825
Mechanical 15:
  lines w0.1: -0.5,0 0.5,0 ; 0,-0.5 0,0.5 ; -5.45,-5.45 5.45,-5.45 5.45,5.45 -5.45,5.45 -5.45,-5.45
3D body: height 3.94, standoff 0, extent -4.825,-4.825 4.825,4.825

## CC20_M [mm] "20-Pin Ceramic Leaded Chip Carrier (CC20), IPC Low Density"
height 3.94
pads (20):
  oval 0.75x2.6 smd: 1(0,4.45) 2(-1.27,4.45) 3(-2.54,4.45) 9(-2.54,-4.45) 10(-1.27,-4.45) 11(0,-4.45) 12(1.27,-4.45) 13(2.54,-4.45) 19(2.54,4.45) 20(1.27,4.45)
  oval 2.6x0.75 smd: 4(-4.45,2.54) 5(-4.45,1.27) 6(-4.45,0) 7(-4.45,-1.27) 8(-4.45,-2.54) 14(4.45,-2.54) 15(4.45,-1.27) 16(4.45,0) 17(4.45,1.27) 18(4.45,2.54)
Top Overlay:
  circle w0.6: c0,0.75 r0.3
  circle w0.25: c0,6.3 r0.125
  lines w0.2: 2.75,1.75 -2.75,1.75 ; -2.75,1.75 -2.75,-2.75 2.75,-2.75 2.75,2.75 -1.75,2.75 -2.75,1.75
Mechanical 13:
  circle w0.1: c0,3.925 r0.5
  lines w0.1: -4.825,-4.825 4.825,-4.825 4.825,4.825 -4.825,4.825 -4.825,-4.825
Mechanical 15:
  lines w0.1: -0.5,0 0.5,0 ; 0,-0.5 0,0.5 ; -6.25,-6.25 6.25,-6.25 6.25,6.25 -6.25,6.25 -6.25,-6.25
3D body: height 3.94, standoff 0, extent -4.825,-4.825 4.825,4.825

## CC20_N [mm] "20-Pin Ceramic Leaded Chip Carrier (CC20), IPC Medium Density"
height 3.94
pads (20):
  oval 0.65x2.3 smd: 1(0,4.4) 2(-1.27,4.4) 3(-2.54,4.4) 9(-2.54,-4.4) 10(-1.27,-4.4) 11(0,-4.4) 12(1.27,-4.4) 13(2.54,-4.4) 19(2.54,4.4) 20(1.27,4.4)
  oval 2.3x0.65 smd: 4(-4.4,2.54) 5(-4.4,1.27) 6(-4.4,0) 7(-4.4,-1.27) 8(-4.4,-2.54) 14(4.4,-2.54) 15(4.4,-1.27) 16(4.4,0) 17(4.4,1.27) 18(4.4,2.54)
Top Overlay:
  circle w0.6: c0,0.85 r0.3
  circle w0.25: c0,6.1 r0.125
  lines w0.2: 2.85,1.85 -2.85,1.85 ; -2.85,1.85 -2.85,-2.85 2.85,-2.85 2.85,2.85 -1.85,2.85 -2.85,1.85
Mechanical 13:
  circle w0.1: c0,3.925 r0.5
  lines w0.1: -4.825,-4.825 4.825,-4.825 4.825,4.825 -4.825,4.825 -4.825,-4.825
Mechanical 15:
  lines w0.1: -0.5,0 0.5,0 ; 0,-0.5 0,0.5 ; -5.8,-5.8 5.8,-5.8 5.8,5.8 -5.8,5.8 -5.8,-5.8
3D body: height 3.94, standoff 0, extent -4.825,-4.825 4.825,4.825

## CC44_L [mm] "44-Pin Ceramic Chip Carrier Package (CC44), IPC High Density"
height 4.83
pads (44):
  oval 0.65x2 smd: 1(0,8) 2(-1.27,8) 3(-2.54,8) 4(-3.81,8) 5(-5.08,8) 6(-6.35,8) 18(-6.35,-8) 19(-5.08,-8) 20(-3.81,-8) 21(-2.54,-8) 22(-1.27,-8) 23(0,-8) 24(1.27,-8) 25(2.54,-8) 26(3.81,-8) 27(5.08,-8) 28(6.35,-8) 40(6.35,8) 41(5.08,8) 42(3.81,8) 43(2.54,8) 44(1.27,8)
  oval 2x0.65 smd: 7(-8,6.35) 8(-8,5.08) 9(-8,3.81) 10(-8,2.54) 11(-8,1.27) 12(-8,0) 13(-8,-1.27) 14(-8,-2.54) 15(-8,-3.81) 16(-8,-5.08) 17(-8,-6.35) 29(8,-6.35) 30(8,-5.08) 31(8,-3.81) 32(8,-2.54) 33(8,-1.27) 34(8,0) 35(8,1.27) 36(8,2.54) 37(8,3.81) 38(8,5.08) 39(8,6.35)
Top Overlay:
  circle w0.25: c0,9.55 r0.125
  circle w0.6: c0,4.6 r0.3
  lines w0.2: 6.6,5.6 -6.6,5.6 ; -6.6,5.6 -5.6,6.6 6.6,6.6 6.6,-6.6 -6.6,-6.6 -6.6,5.6
Mechanical 13:
  circle w0.1: c0,7.43 r0.5
  lines w0.1: -8.33,-8.33 -8.33,8.33 8.33,8.33 8.33,-8.33 -8.33,-8.33
Mechanical 15:
  lines w0.1: -0.5,0 0.5,0 ; 0,-0.5 0,0.5 ; -9.1,-9.1 -9.1,9.1 9.1,9.1 9.1,-9.1 -9.1,-9.1
3D body: height 4.83, standoff 0, extent -8.33,-8.33 8.33,8.33

## CC44_M [mm] "44-Pin Ceramic Chip Carrier Package (CC44), IPC Low Density"
height 4.83
pads (44):
  oval 0.75x2.6 smd: 1(0,8.1) 2(-1.27,8.1) 3(-2.54,8.1) 4(-3.81,8.1) 5(-5.08,8.1) 6(-6.35,8.1) 18(-6.35,-8.1) 19(-5.08,-8.1) 20(-3.81,-8.1) 21(-2.54,-8.1) 22(-1.27,-8.1) 23(0,-8.1) 24(1.27,-8.1) 25(2.54,-8.1) 26(3.81,-8.1) 27(5.08,-8.1) 28(6.35,-8.1) 40(6.35,8.1) 41(5.08,8.1) 42(3.81,8.1) 43(2.54,8.1) 44(1.27,8.1)
  oval 2.6x0.75 smd: 7(-8.1,6.35) 8(-8.1,5.08) 9(-8.1,3.81) 10(-8.1,2.54) 11(-8.1,1.27) 12(-8.1,0) 13(-8.1,-1.27) 14(-8.1,-2.54) 15(-8.1,-3.81) 16(-8.1,-5.08) 17(-8.1,-6.35) 29(8.1,-6.35) 30(8.1,-5.08) 31(8.1,-3.81) 32(8.1,-2.54) 33(8.1,-1.27) 34(8.1,0) 35(8.1,1.27) 36(8.1,2.54) 37(8.1,3.81) 38(8.1,5.08) 39(8.1,6.35)
Top Overlay:
  circle w0.25: c0,9.95 r0.125
  circle w0.6: c0,4.4 r0.3
  lines w0.2: 6.4,5.4 -6.4,5.4 ; -6.4,5.4 -5.4,6.4 6.4,6.4 6.4,-6.4 -6.4,-6.4 -6.4,5.4
Mechanical 13:
  circle w0.1: c0,7.43 r0.5
  lines w0.1: -8.33,-8.33 -8.33,8.33 8.33,8.33 8.33,-8.33 -8.33,-8.33
Mechanical 15:
  lines w0.1: -0.5,0 0.5,0 ; 0,-0.5 0,0.5 ; -9.9,-9.9 -9.9,9.9 9.9,9.9 9.9,-9.9 -9.9,-9.9
3D body: height 4.83, standoff 0, extent -8.33,-8.33 8.33,8.33

## CC44_N [mm] "44-Pin Ceramic Chip Carrier Package (CC44), IPC Medium Density"
height 4.83
pads (44):
  oval 0.65x2.3 smd: 1(0,8.05) 2(-1.27,8.05) 3(-2.54,8.05) 4(-3.81,8.05) 5(-5.08,8.05) 6(-6.35,8.05) 18(-6.35,-8.05) 19(-5.08,-8.05) 20(-3.81,-8.05) 21(-2.54,-8.05) 22(-1.27,-8.05) 23(0,-8.05) 24(1.27,-8.05) 25(2.54,-8.05) 26(3.81,-8.05) 27(5.08,-8.05) 28(6.35,-8.05) 40(6.35,8.05) 41(5.08,8.05) 42(3.81,8.05) 43(2.54,8.05) 44(1.27,8.05)
  oval 2.3x0.65 smd: 7(-8.05,6.35) 8(-8.05,5.08) 9(-8.05,3.81) 10(-8.05,2.54) 11(-8.05,1.27) 12(-8.05,0) 13(-8.05,-1.27) 14(-8.05,-2.54) 15(-8.05,-3.81) 16(-8.05,-5.08) 17(-8.05,-6.35) 29(8.05,-6.35) 30(8.05,-5.08) 31(8.05,-3.81) 32(8.05,-2.54) 33(8.05,-1.27) 34(8.05,0) 35(8.05,1.27) 36(8.05,2.54) 37(8.05,3.81) 38(8.05,5.08) 39(8.05,6.35)
Top Overlay:
  circle w0.25: c0,9.75 r0.125
  circle w0.6: c0,4.5 r0.3
  lines w0.2: 6.5,5.5 -6.5,5.5 ; -6.5,5.5 -5.5,6.5 6.5,6.5 6.5,-6.5 -6.5,-6.5 -6.5,5.5
Mechanical 13:
  circle w0.1: c0,7.43 r0.5
  lines w0.1: -8.33,-8.33 -8.33,8.33 8.33,8.33 8.33,-8.33 -8.33,-8.33
Mechanical 15:
  lines w0.1: -0.5,0 0.5,0 ; 0,-0.5 0,0.5 ; -9.45,-9.45 -9.45,9.45 9.45,9.45 9.45,-9.45 -9.45,-9.45
3D body: height 4.83, standoff 0, extent -8.33,-8.33 8.33,8.33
